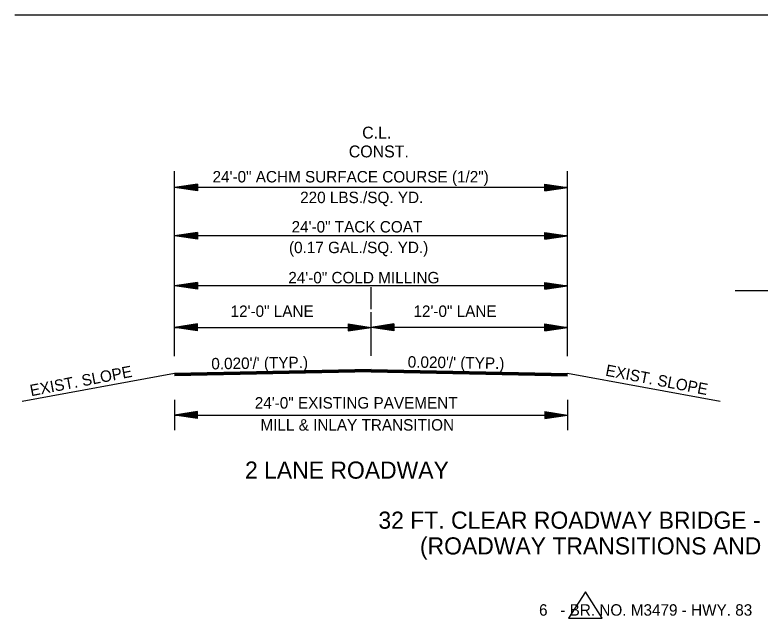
# Model space of a CAD drawing. Extents: x 544259 to 1930787, y -1961343 to 596640.
# Drawn here: x 544317.9 to 544806.9, y -1957307.9 to -1956912.4 of the extents above; entities that cross this region are included whole.
import ezdxf

# ---------------------------------------------------------------- set-up
doc = ezdxf.new("R2010")
doc.units = 0
doc.layers.add('R_Border', color=7, linetype='Continuous')
doc.layers.add('R_Draft', color=7, linetype='Continuous')

msp = doc.modelspace()

# ---------------------------------------------------------------- linework, layer by layer
at = {"layer": 'R_Border'}
for p, q in [((544317.87, -1956912.4), (545239.45, -1956912.4)), ((544825.55, -1957093.35), (544790.55, -1957093.35)), ((544692.29, -1957290.58), (544681.25, -1957307.88)), ((544703.33, -1957307.88), (544692.29, -1957290.58)), ((544681.25, -1957307.88), (544703.33, -1957307.88))]:
    msp.add_line(p, q, dxfattribs=at)
at = {"layer": 'R_Draft'}
for p, q in [((544422.59, -1957136.11), (544422.59, -1957014.74)), ((544680.59, -1957136.11), (544680.59, -1957014.74)), ((544437.59, -1957023.29), (544422.59, -1957025.54)), ((544437.59, -1957023.66), (544425.1, -1957025.54)), ((544437.59, -1957023.29), (544437.59, -1957027.79)), ((544665.59, -1957023.29), (544680.59, -1957025.54)), ((544665.59, -1957027.79), (544665.59, -1957023.29)), ((544665.59, -1957023.66), (544678.09, -1957025.54)), ((544680.59, -1957025.54), (544422.59, -1957025.54)), ((544437.59, -1957027.79), (544422.59, -1957025.54)), ((544437.59, -1957027.41), (544425.1, -1957025.54)), ((544437.59, -1957024.05), (544427.68, -1957025.54)), ((544437.59, -1957027.03), (544427.68, -1957025.54)), ((544437.59, -1957024.42), (544430.18, -1957025.54)), ((544437.59, -1957026.66), (544430.18, -1957025.54)), ((544437.59, -1957024.81), (544432.72, -1957025.54)), ((544437.59, -1957026.27), (544432.72, -1957025.54)), ((544437.59, -1957025.19), (544435.22, -1957025.54)), ((544437.59, -1957025.89), (544435.22, -1957025.54)), ((544665.59, -1957024.05), (544675.51, -1957025.54)), ((544665.59, -1957024.42), (544673.01, -1957025.54)), ((544665.59, -1957024.8), (544670.47, -1957025.54)), ((544665.59, -1957025.19), (544667.96, -1957025.54)), ((544665.59, -1957027.79), (544680.59, -1957025.54)), ((544665.59, -1957026.27), (544670.47, -1957025.54)), ((544665.59, -1957027.03), (544675.51, -1957025.54)), ((544665.59, -1957027.41), (544678.09, -1957025.54)), ((544665.59, -1957026.66), (544673.01, -1957025.54)), ((544665.59, -1957025.89), (544667.96, -1957025.54)), ((544437.59, -1957055), (544422.59, -1957057.25)), ((544680.59, -1957057.25), (544422.59, -1957057.25)), ((544437.59, -1957059.5), (544422.59, -1957057.25)), ((544437.59, -1957055.37), (544425.1, -1957057.25)), ((544437.59, -1957059.12), (544425.1, -1957057.25)), ((544437.59, -1957055.75), (544427.68, -1957057.25)), ((544437.59, -1957058.74), (544427.68, -1957057.25)), ((544437.59, -1957056.13), (544430.18, -1957057.25)), ((544437.59, -1957058.36), (544430.18, -1957057.25)), ((544437.59, -1957056.52), (544432.72, -1957057.25)), ((544437.59, -1957057.98), (544432.72, -1957057.25)), ((544437.59, -1957056.89), (544435.22, -1957057.25)), ((544437.59, -1957057.6), (544435.22, -1957057.25)), ((544437.59, -1957055), (544437.59, -1957059.5)), ((544665.59, -1957055), (544680.59, -1957057.25)), ((544665.59, -1957059.5), (544665.59, -1957055)), ((544665.59, -1957055.37), (544678.09, -1957057.25)), ((544665.59, -1957055.75), (544675.51, -1957057.25)), ((544665.59, -1957056.13), (544673.01, -1957057.25)), ((544665.59, -1957056.51), (544670.47, -1957057.25)), ((544665.59, -1957056.89), (544667.96, -1957057.25)), ((544665.59, -1957059.5), (544680.59, -1957057.25)), ((544665.59, -1957057.97), (544670.47, -1957057.25)), ((544665.59, -1957058.74), (544675.51, -1957057.25)), ((544665.59, -1957059.12), (544678.09, -1957057.25)), ((544665.59, -1957058.36), (544673.01, -1957057.25)), ((544665.59, -1957057.6), (544667.96, -1957057.25)), ((544437.59, -1957087.82), (544422.59, -1957090.07)), ((544680.59, -1957090.07), (544422.59, -1957090.07)), ((544437.59, -1957092.32), (544422.59, -1957090.07)), ((544437.59, -1957088.19), (544425.1, -1957090.07)), ((544437.59, -1957091.94), (544425.1, -1957090.07)), ((544437.59, -1957088.57), (544427.68, -1957090.07)), ((544437.59, -1957091.56), (544427.68, -1957090.07)), ((544437.59, -1957088.95), (544430.18, -1957090.07)), ((544437.59, -1957091.18), (544430.18, -1957090.07)), ((544437.59, -1957089.34), (544432.72, -1957090.07)), ((544437.59, -1957090.8), (544432.72, -1957090.07)), ((544437.59, -1957089.71), (544435.22, -1957090.07)), ((544437.59, -1957090.42), (544435.22, -1957090.07)), ((544437.59, -1957087.82), (544437.59, -1957092.32)), ((544551.59, -1957105.27), (544551.59, -1957090.8)), ((544665.59, -1957087.82), (544680.59, -1957090.07)), ((544665.59, -1957092.32), (544665.59, -1957087.82)), ((544665.59, -1957088.19), (544678.09, -1957090.07)), ((544665.59, -1957088.57), (544675.51, -1957090.07)), ((544665.59, -1957088.95), (544673.01, -1957090.07)), ((544665.59, -1957089.33), (544670.47, -1957090.07)), ((544665.59, -1957089.71), (544667.96, -1957090.07)), ((544665.59, -1957092.32), (544680.59, -1957090.07)), ((544665.59, -1957090.79), (544670.47, -1957090.07)), ((544665.59, -1957091.56), (544675.51, -1957090.07)), ((544665.59, -1957091.94), (544678.09, -1957090.07)), ((544665.59, -1957091.18), (544673.01, -1957090.07)), ((544665.59, -1957090.42), (544667.96, -1957090.07)), ((544551.59, -1957105.27), (544551.59, -1957095.4)), ((544551.59, -1957135.94), (544551.59, -1957107.39)), ((544437.59, -1957115.04), (544422.59, -1957117.29)), ((544437.59, -1957115.41), (544425.1, -1957117.29)), ((544437.59, -1957115.79), (544427.68, -1957117.29)), ((544437.59, -1957116.17), (544430.18, -1957117.29)), ((544437.59, -1957116.55), (544432.72, -1957117.29)), ((544437.59, -1957119.54), (544437.59, -1957115.04)), ((544536.59, -1957115.04), (544551.59, -1957117.29)), ((544536.59, -1957115.04), (544536.59, -1957119.54)), ((544536.59, -1957115.41), (544549.09, -1957117.29)), ((544536.59, -1957115.79), (544546.51, -1957117.29)), ((544536.59, -1957116.17), (544544.01, -1957117.29)), ((544536.59, -1957116.56), (544541.47, -1957117.29)), ((544566.59, -1957115.04), (544551.59, -1957117.29)), ((544566.59, -1957115.41), (544554.1, -1957117.29)), ((544566.59, -1957115.79), (544556.68, -1957117.29)), ((544566.59, -1957116.17), (544559.18, -1957117.29)), ((544566.59, -1957116.56), (544561.72, -1957117.29)), ((544566.59, -1957115.04), (544566.59, -1957119.54)), ((544665.59, -1957115.04), (544680.59, -1957117.29)), ((544665.59, -1957119.54), (544665.59, -1957115.04)), ((544665.59, -1957115.41), (544678.09, -1957117.29)), ((544665.59, -1957115.79), (544675.51, -1957117.29)), ((544665.59, -1957116.17), (544673.01, -1957117.29)), ((544665.59, -1957116.55), (544670.47, -1957117.29)), ((544437.59, -1957119.54), (544422.59, -1957117.29)), ((544422.59, -1957117.29), (544551.59, -1957117.29)), ((544437.59, -1957119.16), (544425.1, -1957117.29)), ((544437.59, -1957118.78), (544427.68, -1957117.29)), ((544437.59, -1957118.4), (544430.18, -1957117.29)), ((544437.59, -1957118.01), (544432.72, -1957117.29)), ((544437.59, -1957116.93), (544435.22, -1957117.29)), ((544437.59, -1957117.64), (544435.22, -1957117.29)), ((544536.59, -1957116.93), (544538.96, -1957117.29)), ((544536.59, -1957119.54), (544551.59, -1957117.29)), ((544536.59, -1957118.02), (544541.47, -1957117.29)), ((544536.59, -1957118.78), (544546.51, -1957117.29)), ((544536.59, -1957119.16), (544549.09, -1957117.29)), ((544536.59, -1957118.4), (544544.01, -1957117.29)), ((544536.59, -1957117.64), (544538.96, -1957117.29)), ((544680.59, -1957117.29), (544551.59, -1957117.29)), ((544566.59, -1957119.54), (544551.59, -1957117.29)), ((544566.59, -1957119.16), (544554.1, -1957117.29)), ((544566.59, -1957118.78), (544556.68, -1957117.29)), ((544566.59, -1957118.4), (544559.18, -1957117.29)), ((544566.59, -1957118.02), (544561.72, -1957117.29)), ((544566.59, -1957116.93), (544564.22, -1957117.29)), ((544566.59, -1957117.64), (544564.22, -1957117.29)), ((544665.59, -1957116.93), (544667.96, -1957117.29)), ((544665.59, -1957119.54), (544680.59, -1957117.29)), ((544665.59, -1957118.01), (544670.47, -1957117.29)), ((544665.59, -1957118.78), (544675.51, -1957117.29)), ((544665.59, -1957119.16), (544678.09, -1957117.29)), ((544665.59, -1957118.4), (544673.01, -1957117.29)), ((544665.59, -1957117.64), (544667.96, -1957117.29)), ((544551.59, -1957144.89), (544422.59, -1957147.47)), ((544551.6, -1957145.19), (544422.59, -1957147.77)), ((544551.61, -1957145.49), (544422.59, -1957148.07)), ((544551.61, -1957145.79), (544422.59, -1957148.37)), ((544551.62, -1957146.09), (544422.59, -1957148.67)), ((544551.57, -1957146.09), (544680.59, -1957148.67)), ((544551.58, -1957145.49), (544680.59, -1957148.07)), ((544551.58, -1957145.79), (544680.59, -1957148.37)), ((544551.59, -1957144.89), (544680.59, -1957147.47)), ((544551.59, -1957145.19), (544680.59, -1957147.77)), ((544422.59, -1957147.47), (544322.53, -1957165.85)), ((544551.62, -1957146.39), (544422.59, -1957148.97)), ((544551.56, -1957146.39), (544680.59, -1957148.97)), ((544680.59, -1957147.27), (544780.66, -1957165.65)), ((544422.59, -1957164.75), (544422.59, -1957184.75)), ((544680.59, -1957164.75), (544680.59, -1957184.75)), ((544437.59, -1957172.5), (544422.59, -1957174.75)), ((544422.59, -1957174.75), (544680.59, -1957174.75)), ((544437.59, -1957177), (544422.59, -1957174.75)), ((544437.59, -1957172.88), (544425.1, -1957174.75)), ((544437.59, -1957176.63), (544425.1, -1957174.75)), ((544437.59, -1957173.26), (544427.68, -1957174.75)), ((544437.59, -1957176.24), (544427.68, -1957174.75)), ((544437.59, -1957173.63), (544430.18, -1957174.75)), ((544437.59, -1957175.87), (544430.18, -1957174.75)), ((544437.59, -1957174.02), (544432.72, -1957174.75)), ((544437.59, -1957175.48), (544432.72, -1957174.75)), ((544437.59, -1957174.4), (544435.22, -1957174.75)), ((544437.59, -1957175.1), (544435.22, -1957174.75)), ((544437.59, -1957177), (544437.59, -1957172.5)), ((544665.59, -1957172.5), (544680.59, -1957174.75)), ((544665.59, -1957172.5), (544665.59, -1957177)), ((544665.59, -1957172.88), (544678.09, -1957174.75)), ((544665.59, -1957173.26), (544675.51, -1957174.75)), ((544665.59, -1957173.63), (544673.01, -1957174.75)), ((544665.59, -1957174.02), (544670.47, -1957174.75)), ((544665.59, -1957174.4), (544667.96, -1957174.75)), ((544665.59, -1957177), (544680.59, -1957174.75)), ((544665.59, -1957175.49), (544670.47, -1957174.75)), ((544665.59, -1957176.24), (544675.51, -1957174.75)), ((544665.59, -1957176.63), (544678.09, -1957174.75)), ((544665.59, -1957175.87), (544673.01, -1957174.75)), ((544665.59, -1957175.1), (544667.96, -1957174.75))]:
    msp.add_line(p, q, dxfattribs=at)

# ---------------------------------------------------------------- texts
for s, height, p in [('C.L.', 7.8, (544545.75, -1956993.45)), ('CONST.', 7.8, (544536.97, -1957005.82)), ('24\'-0" ACHM SURFACE COURSE (1/2")', 7.5, (544447.59, -1957022.24)), ('220 LBS./SQ. YD. ', 7.5, (544505.05, -1957035.79)), ('24\'-0" TACK COAT', 7.5, (544499.45, -1957055.06)), ('(0.17 GAL./SQ. YD.)', 7.5, (544497.72, -1957068.6)), ('24\'-0" COLD MILLING', 7.5, (544497.28, -1957088.4)), ('12\'-0" LANE', 7.5, (544459.41, -1957110.42)), ('12\'-0" LANE', 7.5, (544579.41, -1957110.42)), ('24\'-0" EXISTING PAVEMENT ', 7.5, (544475.27, -1957170.51)), ('MILL & INLAY TRANSITION', 7.5, (544478.99, -1957184.95)), ('2 LANE ROADWAY', 11.25, (544468.87, -1957216.47)), ('32 FT. CLEAR ROADWAY BRIDGE - HYDRODEMOLITION', 11.25, (544556.41, -1957249.31)), ('(ROADWAY TRANSITIONS AND NEW GUARDRAIL)', 11.25, (544583.65, -1957266.18)), ('      6   - BR. NO. M3479 - HWY. 83', 7.5, (544645.1, -1957306.3))]:
    msp.add_text(s, height=height, dxfattribs=at).set_placement(p)
for s, rotation, p in [("0.020'/' (TYP.)", 0.8719, (544446.82, -1957144.85)), ("0.020'/' (TYP.)", 359.1281, (544575.59, -1957143.62)), ('EXIST. SLOPE', 10.8829, (544328.51, -1957162.47)), ('EXIST. SLOPE', 349.1171, (544704.98, -1957148.87))]:
    msp.add_text(s, height=7.5, rotation=rotation, dxfattribs=at).set_placement(p)

doc.saveas('drawing.dxf')
